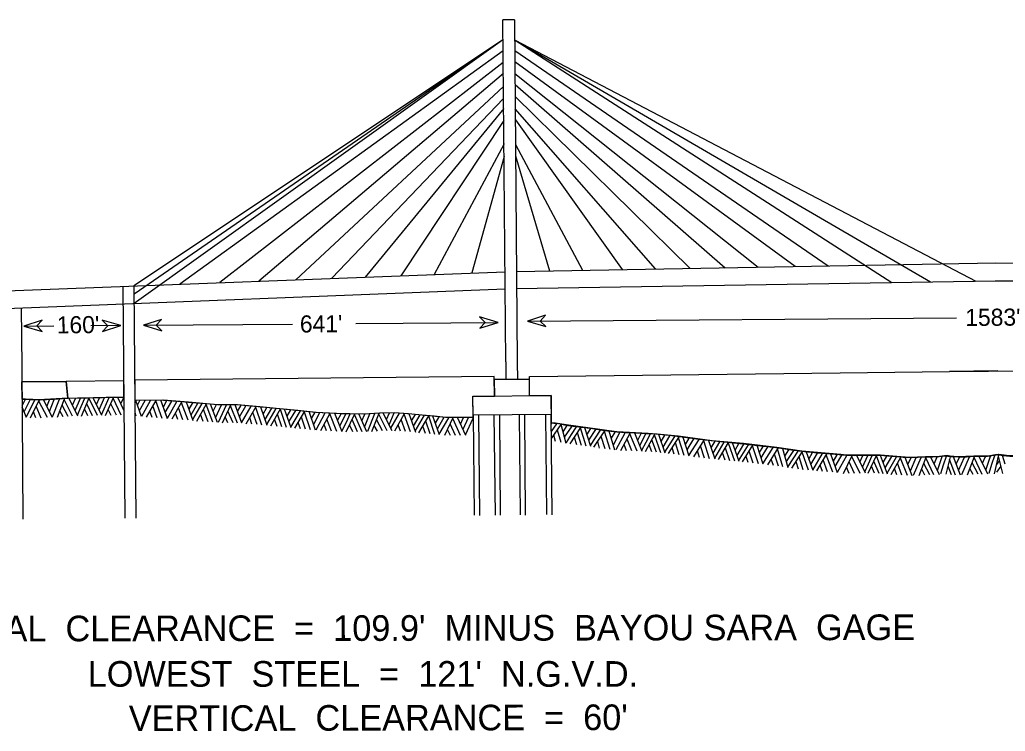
# Model space of a CAD drawing. Extents: x 3250478 to 3288318, y 788638 to 816472.
# Drawn here: x 3256355 to 3261426, y 807842 to 811502 of the extents above; entities that cross this region are included whole.
import ezdxf

# ---------------------------------------------------------------- set-up
doc = ezdxf.new("R2010")
doc.units = 0
doc.layers.add('V-ANNO-SYMB', color=7, linetype='Continuous')

msp = doc.modelspace()

# ---------------------------------------------------------------- linework, layer by layer
at = {"layer": 'V-ANNO-SYMB'}
for p, q in [((3258901.1, 811501.8), (3258841.2, 811501.3)), ((3258901.1, 811501.8), (3258914.8, 809741.8)), ((3258839.7, 811396.7), (3256942.7, 810132.6)), ((3258839.7, 811396.7), (3256943.1, 810090.4)), ((3258839.7, 811396.7), (3256943.5, 810042.7)), ((3258903.6, 811397.3), (3260841.5, 810150.3)), ((3258903.6, 811397.3), (3261041.2, 810153.5)), ((3258903.6, 811397.3), (3261275, 810157.3)), ((3258842.6, 811340.9), (3257179.1, 810141.6)), ((3258902.3, 811344), (3260514, 810235.4)), ((3258843.2, 811281.8), (3257385.1, 810149.5)), ((3260344.3, 810232.4), (3258902.8, 811284.8)), ((3258843.7, 811225.2), (3257585.6, 810157.2)), ((3258903.2, 811225.7), (3260154.1, 810229)), ((3258844.2, 811158.3), (3257776.1, 810164.5)), ((3258903.7, 811169.1), (3259984.4, 810226.1)), ((3258844.8, 811096.6), (3257961.1, 810171.6)), ((3258904.2, 811107.4), (3259804.4, 810222.9)), ((3258845.2, 811045.2), (3258133.2, 810178.2)), ((3259627, 810219.8), (3258904.7, 811043.1)), ((3258845.8, 810983.5), (3258315.6, 810185.2)), ((3258905.1, 810986.5), (3259454.7, 810216.8)), ((3258846.9, 810862.6), (3258487.9, 810191.8)), ((3258906.1, 810860.5), (3259250.3, 810213.2)), ((3258847.4, 810798.3), (3258680.8, 810199.2)), ((3258906.5, 810801.4), (3259080.4, 810210.2)), ((3258911.2, 810207.3), (3261377.1, 810250.5)), ((3261377.1, 810250.5), (3263810.3, 810248.8)), ((3255024.8, 810059), (3258852.7, 810205.8)), ((3256885.8, 810130.4), (3256889.2, 809724.7)), ((3256942.7, 810132.6), (3256946.2, 809725.2)), ((3258911.9, 810119), (3261374.5, 810158.9)), ((3261374.5, 810158.9), (3263811.1, 810159.4)), ((3255026.6, 809967.5), (3258853.5, 810117.6)), ((3256362.5, 810019.9), (3256365, 809720.3)), ((3258721.2, 809972.8), (3258750.4, 809944.3)), ((3258816.3, 809944.9), (3258721.2, 809972.8)), ((3259061, 809981.4), (3258967, 809951.1)), ((3258967, 809951.1), (3261174.5, 809969)), ((3259033, 809951.7), (3259061, 809981.4)), ((3256470.2, 809956.7), (3256376.2, 809926.3)), ((3256376.2, 809926.3), (3256530.1, 809927.6)), ((3256376.2, 809926.3), (3256471.3, 809898.5)), ((3256442.2, 809927), (3256470.2, 809956.7)), ((3256471.3, 809898.5), (3256442.2, 809927)), ((3256874.5, 809928.1), (3256720.7, 809926.8)), ((3256779.4, 809956), (3256808.5, 809927.4)), ((3256874.5, 809928.1), (3256779.4, 809956)), ((3256780.6, 809897.8), (3256874.5, 809928.1)), ((3256808.5, 809927.4), (3256780.6, 809897.8)), ((3257085.2, 809960.4), (3256991.3, 809930)), ((3256991.3, 809930), (3257759.1, 809936.3)), ((3256991.3, 809930), (3257086.4, 809902.2)), ((3257057.3, 809930.7), (3257085.2, 809960.4)), ((3257086.4, 809902.2), (3257057.3, 809930.7)), ((3258084.1, 809938.9), (3258816.3, 809944.9)), ((3258722.4, 809914.6), (3258816.3, 809944.9)), ((3258750.4, 809944.3), (3258722.4, 809914.6)), ((3258967, 809951.1), (3259062.1, 809923.2)), ((3259062.1, 809923.2), (3259033, 809951.7)), ((3256365, 809720.3), (3256371.7, 808933.2)), ((3256889.2, 809724.7), (3256895.8, 808937.7)), ((3256946.2, 809725.2), (3256952.8, 808938.2)), ((3258914.7, 809741.8), (3258915.4, 809651.5)), ((3260576.1, 809685.5), (3261139.1, 809692.4)), ((3261139.1, 809692.4), (3261636.2, 809696.6)), ((3256366.9, 809550), (3256366.1, 809638.5)), ((3256891, 809561), (3256890.3, 809643.8)), ((3258977.4, 809652), (3258796.8, 809650.5)), ((3258796.8, 809650.5), (3258797.5, 809565.8)), ((3258978.1, 809567.3), (3258977.4, 809652)), ((3258687.2, 809565), (3259089.5, 809568.2)), ((3258688, 809468), (3258687.2, 809565)), ((3259089.5, 809568.2), (3259090.3, 809471.2)), ((3256367.1, 809516.3), (3256382.4, 809547.1)), ((3256377.5, 809484.9), (3256408.1, 809546.4)), ((3256388.9, 809457.9), (3256432.9, 809545.7)), ((3256409.7, 809454.4), (3256455.4, 809545)), ((3256465, 809452.8), (3256439.4, 809513.2)), ((3256498.3, 809454.9), (3256453.7, 809540.1)), ((3256523.7, 809456.1), (3256476.8, 809545.8)), ((3256494.7, 809512.7), (3256508.5, 809547.3)), ((3256507.9, 809486.5), (3256533, 809548.5)), ((3256523.8, 809458.5), (3256559.4, 809550.3)), ((3256549, 809457.5), (3256585.9, 809551.9)), ((3256604.3, 809461.1), (3256572.9, 809518.8)), ((3256627.4, 809461.7), (3256584, 809548)), ((3256654.8, 809462.5), (3256609.6, 809553.1)), ((3256626.9, 809518.5), (3256641.8, 809554)), ((3256639.9, 809492.3), (3256666.9, 809554.8)), ((3256651.9, 809468.1), (3256670.9, 809512)), ((3256670.9, 809512), (3256689.4, 809555.4)), ((3256672.3, 809463), (3256712.2, 809556)), ((3256729.7, 809464.5), (3256699.6, 809526.3)), ((3256754.8, 809465.2), (3256711.5, 809553.1)), ((3256777.6, 809465.7), (3256732.8, 809556.8)), ((3256749.6, 809522.1), (3256764.7, 809557.3)), ((3256763.2, 809494.9), (3256790.4, 809558)), ((3256776, 809469), (3256815.2, 809558.5)), ((3256796.7, 809466.2), (3256837.7, 809559)), ((3256852.1, 809467.4), (3256823.3, 809526.4)), ((3256876.5, 809467.5), (3256835.8, 809554.7)), ((3256891.6, 809489.7), (3256859.1, 809559.3)), ((3256875.5, 809525.4), (3256890.8, 809559.4)), ((3256981.8, 809460.2), (3256951.9, 809542.3)), ((3256960.4, 809519), (3256973.7, 809542.6)), ((3256972, 809492.2), (3257000.7, 809543)), ((3256982.8, 809462.7), (3257028.6, 809543.4)), ((3257007.4, 809458.1), (3257056.5, 809543.7)), ((3257062.6, 809453.5), (3257040, 809515.2)), ((3257088.7, 809451.3), (3257055.5, 809542)), ((3257115.8, 809450), (3257081.4, 809544.1)), ((3257116, 809449), (3257081.4, 809544.1)), ((3257094.5, 809509.9), (3257112.6, 809542.4)), ((3257104.2, 809482.2), (3257137.1, 809540.4)), ((3257114.9, 809452.6), (3257163.5, 809538.2)), ((3257139.6, 809448.1), (3257189.9, 809536)), ((3257220.9, 809441.2), (3257187.6, 809531.9)), ((3257248.2, 809438.9), (3257213.5, 809534)), ((3257226.8, 809497.7), (3257245.7, 809531.3)), ((3257237, 809470.2), (3257270.7, 809529.3)), ((3257266.1, 809437.5), (3257315.9, 809525.6)), ((3257270.1, 809486.4), (3257293.2, 809527.5)), ((3257349, 809431), (3257314.8, 809522.9)), ((3257371.8, 809429.2), (3257336.4, 809524.4)), ((3257349.7, 809488.2), (3257368.3, 809521.7)), ((3257362.8, 809453.5), (3257393.9, 809520.8)), ((3257377.3, 809431.8), (3257418.7, 809520.8)), ((3257398.1, 809429), (3257441.3, 809520.8)), ((3257475.8, 809426.6), (3257439.2, 809516.2)), ((3257497, 809426.1), (3257462.7, 809521.3)), ((3257475.9, 809486.1), (3257494.3, 809518.5)), ((3257485.5, 809458.3), (3257518.7, 809516.4)), ((3257496.1, 809428.7), (3257545.1, 809514)), ((3257520.8, 809423.9), (3257571.6, 809511.7)), ((3256390.3, 809455), (3256367.2, 809509.2)), ((3256438.2, 809453.6), (3256425.1, 809484.8)), ((3256578.4, 809459.4), (3256561.8, 809490.1)), ((3256705.7, 809463.9), (3256688.1, 809499.7)), ((3256825.2, 809466.8), (3256810.6, 809497.3)), ((3256887.5, 809498.6), (3256891.4, 809507.2)), ((3256954.5, 809462.5), (3256948.2, 809479.6)), ((3257036.7, 809455.7), (3257024.9, 809488.4)), ((3257168.8, 809445.6), (3257157, 809478.4)), ((3257194.7, 809443.4), (3257172.2, 809505.2)), ((3257246.4, 809444.8), (3257270.1, 809486.4)), ((3257299.4, 809434.8), (3257285.8, 809472.2)), ((3257324, 809432.9), (3257300.3, 809497.4)), ((3257426.6, 809428.9), (3257412.7, 809459.8)), ((3257453, 809428.8), (3257426, 809488.6)), ((3257576, 809419.1), (3257553.7, 809480.9)), ((3257601.6, 809416.7), (3257569.2, 809507.7)), ((3257628.9, 809414.1), (3257595.1, 809509.6)), ((3257608.1, 809473.1), (3257627.2, 809506.5)), ((3257617.8, 809445.5), (3257652.2, 809504.2)), ((3257626.9, 809420), (3257651.1, 809461.3)), ((3257646.5, 809412.5), (3257697.4, 809500)), ((3257651.1, 809461.3), (3257674.7, 809502.1)), ((3257703.5, 809407.1), (3257681.2, 809472)), ((3257728.5, 809404.6), (3257696.3, 809497.2)), ((3257751.2, 809402.4), (3257717.9, 809498.3)), ((3257730.4, 809461.8), (3257749.7, 809494.9)), ((3257740.5, 809433), (3257775.2, 809492.4)), ((3257750.1, 809405.4), (3257799.9, 809489.9)), ((3257770.6, 809400.5), (3257822.4, 809487.8)), ((3257851.8, 809392.6), (3257819.9, 809483.4)), ((3257877.1, 809390.2), (3257843.7, 809485.7)), ((3257856.6, 809450.4), (3257875.2, 809482.7)), ((3257868.3, 809422), (3257899.7, 809481.1)), ((3257879.8, 809392.8), (3257926.2, 809479.6)), ((3257904.7, 809388.8), (3257952.6, 809478.1)), ((3257986.2, 809384.2), (3257950.4, 809473.9)), ((3258013.5, 809382.6), (3257976.3, 809476.7)), ((3257990.5, 809440.8), (3258008.5, 809474.9)), ((3258002.4, 809410.7), (3258033.6, 809474.7)), ((3258035, 809382.8), (3258078.9, 809474)), ((3258035.8, 809431.9), (3258056.1, 809474.4)), ((3258117.7, 809381.5), (3258078, 809471.2)), ((3258140.6, 809381.2), (3258099.5, 809474)), ((3258114.9, 809438.6), (3258131.4, 809473.2)), ((3258129.8, 809405.6), (3258157.1, 809474.9)), ((3258145.6, 809385.1), (3258181.9, 809476.3)), ((3258166.6, 809383.5), (3258204.4, 809477.6)), ((3258245.7, 809387), (3258202.5, 809473)), ((3258271.1, 809387.8), (3258225.7, 809478.3)), ((3258243, 809444.9), (3258257.4, 809479.3)), ((3258255.8, 809418.4), (3258281.9, 809480)), ((3258264.8, 809400.4), (3258308.4, 809478.2)), ((3258285.1, 809387.9), (3258334.8, 809476.2)), ((3258366.5, 809381.6), (3258332.5, 809472.1)), ((3258392.4, 809379), (3258358.4, 809474.3)), ((3258371.4, 809437.9), (3258390.6, 809471.4)), ((3258381.2, 809410.4), (3258415.6, 809469.1)), ((3258408.9, 809377.5), (3258460.7, 809464.5)), ((3258414, 809426.4), (3258438, 809466.9)), ((3258491.2, 809369), (3258459.5, 809461.8)), ((3258514.6, 809366.8), (3258481.2, 809462.6)), ((3259090.3, 809471.2), (3258688, 809468)), ((3258688, 809468), (3258693.4, 808952.9)), ((3258721.7, 808952.1), (3258717.4, 809468.2)), ((3258795.3, 809468.8), (3258800.7, 808953.8)), ((3258829, 808953), (3258824.7, 809469.1)), ((3258924, 809469.9), (3258929.4, 808954.9)), ((3258957.7, 808954), (3258953.4, 809470.1)), ((3259060.9, 809471), (3259066.3, 808956)), ((3259094.6, 808955.1), (3259090.3, 809471.2)), ((3257550.1, 809421.4), (3257538.4, 809454.2)), ((3257679.8, 809409.4), (3257666.7, 809447)), ((3257799, 809397.7), (3257788.1, 809429.8)), ((3257825.7, 809395.2), (3257804.2, 809457.2)), ((3257934.1, 809387.1), (3257921.3, 809419.6)), ((3257960, 809385.6), (3257935.7, 809446.7)), ((3258012.8, 809384.6), (3258035.8, 809431.9)), ((3258068.4, 809382.3), (3258052.4, 809418.8)), ((3258092.6, 809381.9), (3258065.1, 809444.8)), ((3258195.1, 809385.1), (3258179.3, 809415)), ((3258221.8, 809386.6), (3258191.1, 809444.6)), ((3258314.4, 809385.6), (3258302.4, 809418.3)), ((3258340.3, 809383.6), (3258317.3, 809445.2)), ((3258390.3, 809384.9), (3258414.5, 809426.2)), ((3258442.1, 809374.1), (3258429.4, 809411.8)), ((3258466.2, 809371.6), (3258444.3, 809436.7)), ((3258493.7, 809426.2), (3258512.9, 809459.3)), ((3258503.8, 809397.4), (3258538.5, 809456.8)), ((3258513.4, 809369.8), (3258563.2, 809454.4)), ((3258542.2, 809364.1), (3258585.8, 809455.7)), ((3258597.5, 809363.7), (3258570.5, 809423.5)), ((3258623.8, 809363.6), (3258583.8, 809451.1)), ((3258650.4, 809363.9), (3258607.2, 809455.4)), ((3258623.7, 809421.6), (3258638.9, 809455.7)), ((3258635.9, 809394.9), (3258663.4, 809455.8)), ((3258649.2, 809366.4), (3258688.2, 809452.2)), ((3259090.7, 809422.9), (3259093.6, 809427.3)), ((3259091, 809382.9), (3259118.2, 809423.5)), ((3259091.3, 809347), (3259140.4, 809420.1)), ((3259167.1, 809322.4), (3259140.4, 809420.1)), ((3259150.6, 809382.8), (3259172.2, 809414.7)), ((3259158.3, 809354.6), (3259197, 809410.5)), ((3258570.7, 809363.9), (3258556.9, 809394.8)), ((3259112, 809331.5), (3259102.9, 809364.1)), ((3259140.8, 809327.4), (3259121.3, 809390.1)), ((3259168.7, 809327.6), (3259194.3, 809368)), ((3259188, 809319.4), (3259242, 809405)), ((3259194.3, 809368), (3259219.4, 809407.9)), ((3259245.2, 809311.9), (3259224.9, 809377.6)), ((3259270.3, 809308.8), (3259240.8, 809402.3)), ((3259293, 809305.9), (3259262.4, 809402.7)), ((3259273.8, 809365.8), (3259294.1, 809398.4)), ((3259282.5, 809338.9), (3259319.5, 809394.6)), ((3259291.2, 809311.6), (3259344, 809390.9)), ((3259309.7, 809303.2), (3259366.3, 809387.4)), ((3259392.7, 809291.4), (3259363.7, 809383.2)), ((3259417.9, 809288.2), (3259387.5, 809384.7)), ((3259399.3, 809349), (3259418.9, 809380.7)), ((3259409.6, 809314.7), (3259443.4, 809378.7)), ((3259423.7, 809290.4), (3259469.9, 809377.3)), ((3259448.6, 809286.4), (3259496.4, 809375.8)), ((3259531.5, 809282.8), (3259494.2, 809371.9)), ((3259558, 809281.4), (3259520.1, 809375.2)), ((3259534.6, 809339.4), (3259552.3, 809373.7)), ((3259545.5, 809312.3), (3259577.3, 809372.4)), ((3259574.5, 809280.5), (3259622.6, 809369.6)), ((3259577.6, 809329.5), (3259599.8, 809371)), ((3259653.3, 809274.4), (3259621.5, 809367.1)), ((3259676, 809272.1), (3259643.1, 809368.1)), ((3259655.4, 809331.5), (3259674.9, 809364.5)), ((3259665.4, 809302.7), (3259700.4, 809361.9)), ((3259674.2, 809277.4), (3259725, 809358.8)), ((3259221.1, 809315.1), (3259209.4, 809353.1)), ((3259337.9, 809298.8), (3259328.8, 809331.4)), ((3259366.7, 809294.8), (3259347.2, 809357.4)), ((3259477.9, 809284.8), (3259465.2, 809317.3)), ((3259505.3, 809283.8), (3259480, 809344.5)), ((3259555.7, 809287.2), (3259578.1, 809329.5)), ((3259607.9, 809278.5), (3259593.6, 809315.7)), ((3259632.1, 809277), (3259607.4, 809341.1)), ((3259693.3, 809270.1), (3259747.4, 809356)), ((3259748.2, 809263.3), (3259728.4, 809325.9)), ((3259774, 809260), (3259744.9, 809351.8)), ((3259799.2, 809256.8), (3259768.6, 809353.3)), ((3259780.5, 809317.6), (3259800.1, 809349.3)), ((3259789, 809289.5), (3259824.4, 809346.2)), ((3259798.4, 809259.5), (3259850.7, 809342.9)), ((3259823.3, 809253.7), (3259877.1, 809339.7)), ((3259878.2, 809246.9), (3259858.1, 809309.5)), ((3259904.3, 809243.7), (3259874.5, 809335.7)), ((3259933.7, 809240.8), (3259900.5, 809336.5)), ((3259913.2, 809299.9), (3259932.6, 809333.3)), ((3259922.8, 809272.3), (3259957.6, 809330.8)), ((3259951.3, 809239.1), (3260002.7, 809326.3)), ((3259956.2, 809287.9), (3259980, 809328.5)), ((3260034, 809231), (3260001.6, 809323.5)), ((3260056.7, 809228.8), (3260023.2, 809324.6)), ((3260035.7, 809288.2), (3260055, 809321.3)), ((3260045.9, 809259.4), (3260080.5, 809318.8)), ((3260054, 809232.2), (3260105.2, 809315.9)), ((3260074.4, 809227), (3260127.6, 809313.4)), ((3260155.5, 809217.7), (3260125.1, 809309.1)), ((3260180, 809214.8), (3260148.9, 809311.1)), ((3259721.6, 809266.6), (3259711.6, 809298.9)), ((3259852.4, 809250.1), (3259841.9, 809283.4)), ((3259931.7, 809246.8), (3259956.2, 809287.9)), ((3259984.5, 809235.8), (3259971.7, 809273.5)), ((3260009, 809233.4), (3259986.6, 809298.3)), ((3260129.4, 809220.7), (3260108.9, 809283.1)), ((3260160.9, 809275.4), (3260180.3, 809307.3)), ((3260169.6, 809247.4), (3260204.7, 809304.3)), ((3260179.2, 809217.5), (3260231, 809301.1)), ((3260203.8, 809211.9), (3260257.4, 809297.9)), ((3260258.7, 809205.2), (3260238.5, 809267.7)), ((3260282.1, 809201.4), (3260254.8, 809294.1)), ((3260309.2, 809197.3), (3260280.8, 809294.5)), ((3260291.7, 809257.4), (3260312.7, 809289.7)), ((3260299.9, 809229.3), (3260337.5, 809286)), ((3260328.3, 809194.7), (3260382.5, 809280.2)), ((3260334.7, 809243.4), (3260359.9, 809283.2)), ((3260414.4, 809184.7), (3260381.3, 809277)), ((3260437.2, 809182.7), (3260402.9, 809278.2)), ((3260415.8, 809241.9), (3260434.7, 809275.1)), ((3260426.1, 809213.2), (3260460.3, 809272.9)), ((3260436.2, 809185.6), (3260485.1, 809270.7)), ((3260456.7, 809181), (3260507.5, 809268.8)), ((3260538, 809173.9), (3260505.1, 809264.4)), ((3260563.1, 809171.7), (3260528.8, 809266.9)), ((3260542, 809231.7), (3260560.4, 809264.1)), ((3260579.7, 809253.1), (3260584.8, 809262)), ((3260580.1, 809205.1), (3260611.3, 809259.8)), ((3260594, 809168.1), (3260637.8, 809259.5)), ((3260706.5, 809169.1), (3260661.5, 809259.7)), ((3260678, 809225.2), (3260693.7, 809260.4)), ((3260691.1, 809200.1), (3260718.8, 809260.6)), ((3260720.3, 809169), (3260764.2, 809260.3)), ((3260722, 809217.9), (3260741.3, 809260.8)), ((3260797.7, 809166.6), (3260763.2, 809258.3)), ((3260820.5, 809165), (3260784.7, 809259.9)), ((3260798.1, 809223.8), (3260816.6, 809257.4)), ((3261108.7, 809212.5), (3261123.1, 809257.4)), ((3261325.6, 809185.2), (3261349.2, 809257.4)), ((3261357.3, 809215.3), (3261371.6, 809260.1)), ((3261369.9, 809166.5), (3261393.6, 809263.6)), ((3261414.2, 809166.9), (3261388.9, 809263.7)), ((3261426.1, 809215.9), (3261411, 809260.5)), ((3260102.7, 809223.8), (3260092.3, 809255.9)), ((3260232.9, 809208.3), (3260222.3, 809241.5)), ((3260308.9, 809203.1), (3260334.7, 809243.4)), ((3260361.4, 809190.3), (3260349.7, 809228.4)), ((3260385.4, 809187.1), (3260365.3, 809252.8)), ((3260485.1, 809178.5), (3260473.8, 809210.4)), ((3260511.8, 809176.2), (3260489.7, 809238)), ((3260551.6, 809203.9), (3260579.7, 809253.1)), ((3260649.4, 809167.5), (3260622.3, 809227.4)), ((3260679.2, 809168.3), (3260635.9, 809254.7)), ((3260703, 809176.2), (3260722, 809217.9)), ((3260778, 809168.2), (3260750.3, 809231.1)), ((3260808.6, 809196.6), (3260842.2, 809255.2)), ((3260818.8, 809169.6), (3260866.9, 809253)), ((3260839.3, 809163), (3260889.4, 809251.3)), ((3260894.5, 809158.8), (3260871.8, 809220.3)), ((3260922.1, 809157), (3260887.1, 809246.7)), ((3260947.5, 809155.5), (3260910.7, 809249.8)), ((3260924.8, 809214.9), (3260942.3, 809247.8)), ((3260937.7, 809180.5), (3260966.8, 809249.1)), ((3260954.6, 809159.4), (3260993.4, 809249.8)), ((3260983.3, 809157.6), (3261019.8, 809252.2)), ((3261038.5, 809161.3), (3261006.9, 809219)), ((3261058.7, 809160.4), (3261017.8, 809247.9)), ((3261087.5, 809160.9), (3261043.5, 809252.1)), ((3261060.3, 809217.3), (3261075.7, 809252.6)), ((3261077.1, 809182.4), (3261100.7, 809254.6)), ((3261093.9, 809167), (3261108.7, 809212.5)), ((3261121.4, 809163.7), (3261143.4, 809253.6)), ((3261170.6, 809159.8), (3261139.8, 809238.8)), ((3261196, 809158.3), (3261159.2, 809252.6)), ((3261173.4, 809217.7), (3261190.8, 809250.6)), ((3261186.2, 809183.3), (3261215.4, 809251.8)), ((3261203.1, 809162.1), (3261241.9, 809252.6)), ((3261231.8, 809160.4), (3261268.3, 809255)), ((3261287, 809164.1), (3261255.4, 809221.8)), ((3261307.2, 809163.2), (3261266.3, 809250.7)), ((3261336, 809163.7), (3261292, 809254.9)), ((3261308.9, 809220), (3261324.3, 809255.4)), ((3261342.4, 809169.8), (3261357.3, 809215.3)), ((3261382.5, 809213.2), (3261396.6, 809233.5)), ((3260562.6, 809174.3), (3260580.1, 809205.1)), ((3260623.4, 809167.7), (3260609.2, 809199.6)), ((3260753.7, 809168.5), (3260737.7, 809205)), ((3260867.8, 809160.8), (3260856.2, 809192.6)), ((3261012.6, 809159.6), (3260995.9, 809190.2)), ((3261149.2, 809160.3), (3261131.6, 809205.4)), ((3261261.1, 809162.4), (3261244.5, 809193)), ((3261382.8, 809174.9), (3261404.1, 809205.5))]:
    msp.add_line(p, q, dxfattribs=at)
for points in [[(3258856.8, 809741.3), (3258841.2, 811501.3)], [(3258857.9, 809651.1), (3258857.1, 809741.3)], [(3260579.6, 809264.8), (3260378.8, 809282.8), (3260251, 809301), (3260078.4, 809321.4), (3259918.4, 809336), (3259743.6, 809358.9), (3259635.7, 809370.6), (3259588.4, 809373.9), (3259428.1, 809381.4), (3259375.5, 809388.1), (3259327.5, 809396.1), (3259228, 809408.7), (3259166.6, 809418.2), (3259111.8, 809427), (3259090.7, 809428.8), (3259089.5, 809568.2), (3258978.1, 809567.3), (3258977.3, 809666.9), (3260576.1, 809685.5)], [(3261387.6, 809695.2), (3261139.1, 809692.4)], [(3256594.6, 809641.3), (3256366.1, 809638.5)], [(3256366.1, 809638.5), (3256594.6, 809641.3)], [(3256366.9, 809550), (3256385, 809549.3), (3256460.5, 809546.5), (3256482.1, 809547.6), (3256602, 809554.4), (3256594.6, 809641.3)], [(3256594.6, 809641.3), (3256602, 809554.4), (3256482.1, 809547.6), (3256460.5, 809546.5), (3256385, 809549.3), (3256366.9, 809550)], [(3256890.3, 809643.8), (3256594.6, 809641.3), (3256602, 809554.4), (3256800.2, 809559.5), (3256891, 809561)], [(3256891, 809559.4), (3256853.8, 809559.3), (3256780.5, 809557.7), (3256707.3, 809555.9), (3256652.7, 809554.3), (3256598.2, 809552.7), (3256528.2, 809548.3), (3256458.3, 809544.9), (3256366.9, 809547.6)], [(3258688.2, 809455.7), (3258683.2, 809456), (3258615.4, 809455.5), (3258547.7, 809455.9), (3258487, 809461.8), (3258426.3, 809468.1), (3258355.2, 809474.6), (3258284, 809480.1), (3258205.8, 809477.7), (3258127.6, 809473.3), (3258004, 809475.2), (3257880.6, 809482.2), (3257786.8, 809491.2), (3257693.1, 809500.4), (3257582.3, 809510.8), (3257471.4, 809520.5), (3257425.1, 809520.8), (3257378.8, 809520.8), (3257309.3, 809526.2), (3257239.9, 809531.8), (3257168.2, 809537.8), (3257096.5, 809543.8), (3257091, 809544.2), (3256947.7, 809542.3)], [(3260260.7, 809297.5), (3260169.1, 809308.6), (3260077.5, 809319.1), (3259994.8, 809327.1), (3259912.1, 809335.3), (3259838.1, 809344.5), (3259764.2, 809353.9), (3259696.4, 809362.3), (3259628.5, 809369.3), (3259576.7, 809372.5), (3259524.9, 809375), (3259475.8, 809377), (3259426.7, 809379.7), (3259364.3, 809387.7), (3259302, 809397.3), (3259245.8, 809404.5), (3259189.5, 809411.8), (3259158.6, 809417), (3259127.7, 809422.3), (3259103.5, 809425.5), (3259090.7, 809426.7)], [(3260579.7, 809262.5), (3260571.7, 809263.1), (3260531, 809266.8), (3260462, 809272.7), (3260393.1, 809278.8), (3260326.8, 809287.6), (3260260.7, 809297.5)], [(3261142.8, 809256.2), (3261127.9, 809260.2), (3261088.2, 809254.4), (3261015.1, 809253.8), (3260932.1, 809250.5), (3260784.5, 809261.9), (3260749.6, 809262.4), (3260609.9, 809262.1), (3260579.6, 809264.8)], [(3261142.8, 809253.7), (3261118.6, 809256.8), (3261085.5, 809252.8), (3261052.9, 809252.2), (3261020.4, 809252.2), (3260978.6, 809249.4), (3260936.7, 809248.2), (3260901.4, 809250.4), (3260866.1, 809253.1), (3260822.6, 809256.9), (3260779, 809260.1), (3260731.6, 809260.7), (3260684.2, 809260.4), (3260648.4, 809259.3), (3260612.6, 809259.7), (3260579.7, 809262.5)], [(3261393, 809265.9), (3261390.7, 809266.1), (3261376.4, 809262.9), (3261336.7, 809257.2), (3261263.6, 809256.5), (3261180.6, 809253.3), (3261142.8, 809256.2)], [(3261392.1, 809264.2), (3261390.5, 809264.2), (3261367.1, 809259.6), (3261334, 809255.6), (3261301.5, 809255), (3261268.9, 809255), (3261227.1, 809252.2), (3261185.2, 809251), (3261149.9, 809253.1), (3261142.8, 809253.7)], [(3261392.1, 809264.2), (3261415.5, 809260), (3261448.7, 809256.5), (3261481.2, 809256.5), (3261513.7, 809257.1), (3261555.6, 809255), (3261597.5, 809254.4), (3261632.8, 809257.2), (3261639.9, 809257.9)], [(3261639.8, 809260.4), (3261602.1, 809256.9), (3261519, 809258.7), (3261445.9, 809258.1), (3261406.2, 809263.2), (3261393, 809265.9)]]:
    msp.add_lwpolyline(points, dxfattribs=at)
msp.add_lwpolyline([(3258796.6, 809666.9), (3256946.8, 809648.4), (3256947.7, 809544.2), (3257093.3, 809546.2), (3257222.8, 809535.5), (3257372.8, 809523.3), (3257475.7, 809522.5), (3257590.6, 809511.7), (3257878.5, 809483.9), (3257985.4, 809478.1), (3258124.3, 809475.1), (3258210.4, 809480), (3258282.8, 809481.9), (3258373.2, 809475.1), (3258545.5, 809458.1), (3258684.3, 809457.2), (3258688.1, 809457), (3258687.2, 809565), (3258797.5, 809565.8)], close=True, dxfattribs=at)

# ---------------------------------------------------------------- texts
for s, height, rotation, p in [("1583'", 87.98, 0.4666, (3261220.4, 809926.1)), ("160'", 87.98, 0.4666, (3256545.8, 809888.1)), ("641'", 87.98, 0.4666, (3257796.8, 809892.7)), ("VERTICAL  CLEARANCE  =  109.9'  MINUS  BAYOU SARA  GAGE", 131.91, 0.0865, (3255630, 808302.9)), ("LOWEST  STEEL  =  121'  N.G.V.D.", 131.91, 359.9928, (3256704.7, 808071)), ("VERTICAL  CLEARANCE  =  60'", 131.91, 0.1261, (3256916.2, 807842.3))]:
    msp.add_text(s, height=height, rotation=rotation, dxfattribs=at).set_placement(p)

doc.saveas('drawing.dxf')
